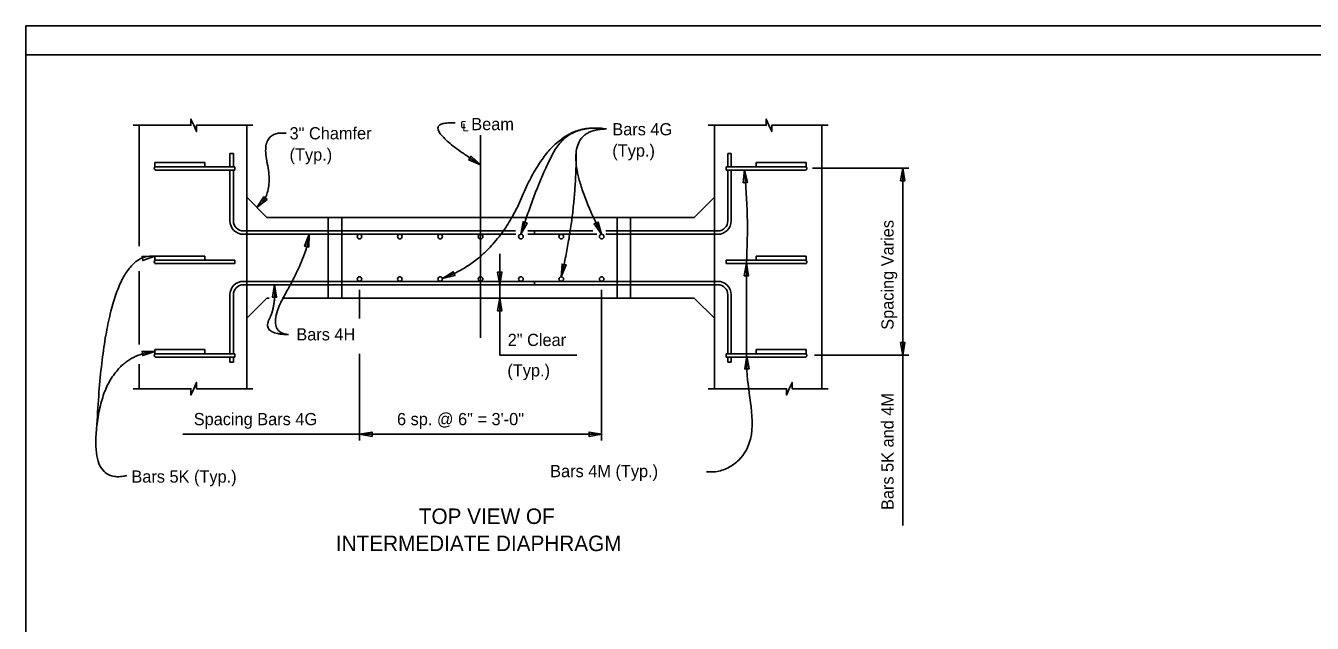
# Model space of a CAD drawing. Extents: x 0 to 30.8, y 0 to 19.8.
# Drawn here: x 0 to 15.94, y 12.4 to 19.8 of the extents above; entities that cross this region are included whole.
import ezdxf

# ---------------------------------------------------------------- set-up
doc = ezdxf.new("R2010")
doc.units = 0
for name, color, linetype in [('ActivePts-ConstElements', 7, 'Continuous'), ('BeamConc', 7, 'Continuous'), ('CL_Major', 7, 'Continuous'), ('Dimension', 7, 'Continuous'), ('Miscellaneous', 7, 'Continuous'), ('Miscellaneous1', 7, 'Continuous'), ('Rebar', 7, 'Continuous'), ('TextStructures', 7, 'Continuous')]:
    doc.layers.add(name, color=color, linetype=linetype)

msp = doc.modelspace()

# ---------------------------------------------------------------- linework, layer by layer
at = {"layer": 'ActivePts-ConstElements'}
msp.add_lwpolyline([(0, 0), (30.765, 0), (30.765, 19.441), (0, 19.441)], close=True, dxfattribs=at)
at = {"layer": 'BeamConc'}
for p, q in [((1.405, 17.069), (1.405, 18.566)), ((2.738, 15.303), (2.738, 18.566)), ((8.53, 18.566), (8.53, 15.303)), ((9.863, 18.566), (9.863, 15.303)), ((2.988, 17.425), (2.738, 17.675)), ((8.53, 17.675), (8.28, 17.425)), ((8.28, 17.425), (2.988, 17.425)), ((1.405, 15.85), (1.405, 16.759)), ((2.988, 16.425), (2.738, 16.175)), ((3.016, 16.425), (2.988, 16.425)), ((8.28, 16.425), (3.175, 16.425)), ((8.53, 16.175), (8.28, 16.425)), ((1.405, 15.303), (1.405, 15.609))]:
    msp.add_line(p, q, dxfattribs=at)
at = {"layer": 'CL_Major'}
msp.add_line((5.634, 15.935), (5.634, 18.446), dxfattribs=at)
at = {"layer": 'Dimension'}
for p, q in [((9.744, 18.035), (10.939, 18.035)), ((10.863, 18.035), (10.863, 13.61)), ((5.872, 16.972), (5.872, 15.719)), ((4.134, 16.528), (4.134, 16.174)), ((7.134, 16.528), (7.134, 14.663)), ((4.134, 15.734), (4.134, 14.663)), ((5.872, 15.719), (6.828, 15.719)), ((9.771, 15.718), (10.939, 15.718)), ((1.945, 14.738), (7.134, 14.738))]:
    msp.add_line(p, q, dxfattribs=at)
for points in [[(2.814, 18.566), (2.115, 18.566), (2.115, 18.488), (2.081, 18.566), (2.047, 18.643), (2.047, 18.566), (1.329, 18.566)], [(9.939, 18.566), (9.24, 18.566), (9.24, 18.489), (9.206, 18.566), (9.172, 18.644), (9.172, 18.566), (8.454, 18.566)], [(2.814, 15.303), (2.115, 15.303), (2.115, 15.38), (2.081, 15.303), (2.047, 15.225), (2.047, 15.303), (1.329, 15.303)], [(9.939, 15.303), (9.492, 15.303), (9.492, 15.38), (9.458, 15.303), (9.424, 15.225), (9.424, 15.303), (8.454, 15.303)]]:
    msp.add_lwpolyline(points, dxfattribs=at)
for points in [[(5.634, 18.077), (5.516, 18.183), (5.488, 18.138)], [(8.904, 18.013), (8.887, 17.855), (8.94, 17.858)], [(10.863, 18.035), (10.89, 17.879), (10.837, 17.879)], [(2.863, 17.55), (2.951, 17.682), (2.989, 17.646)], [(6.134, 17.216), (6.161, 17.372), (6.211, 17.355)], [(3.509, 17.216), (3.454, 17.068), (3.506, 17.058)], [(3.509, 17.216), (3.509, 17.216), (3.509, 17.216)], [(7.134, 17.216), (7.041, 17.345), (7.089, 17.368)], [(1.599, 16.943), (1.441, 16.942), (1.45, 16.89)], [(5.162, 16.67), (5.316, 16.704), (5.296, 16.753)], [(5.872, 16.591), (5.898, 16.748), (5.845, 16.748)], [(6.634, 16.69), (6.696, 16.836), (6.644, 16.848)], [(8.928, 16.859), (8.901, 16.703), (8.954, 16.703)], [(3.082, 16.592), (3.108, 16.436), (3.055, 16.436)], [(5.872, 16.425), (5.845, 16.269), (5.898, 16.269)], [(10.863, 15.718), (10.837, 15.874), (10.89, 15.874)], [(1.599, 15.766), (1.441, 15.765), (1.45, 15.713)], [(8.932, 15.705), (8.906, 15.548), (8.959, 15.548)], [(8.932, 15.705), (8.932, 15.704), (8.932, 15.704)], [(4.134, 14.738), (4.29, 14.765), (4.29, 14.712)], [(7.134, 14.738), (6.978, 14.712), (6.978, 14.765)]]:
    msp.add_lwpolyline(points, close=True, dxfattribs=at)
for points in [[(5.634, 18.077), (4.768, 18.625), (5.321, 18.595)], [(5.162, 16.67), (5.823, 16.905), (6.49, 18.495), (6.985, 18.529)], [(6.134, 17.216), (6.339, 17.859), (6.73, 18.591), (7.195, 18.521)], [(7.134, 17.216), (6.465, 18.521), (7.195, 18.521)], [(2.863, 17.55), (3.077, 17.701), (2.903, 18.503), (3.228, 18.468)], [(6.634, 16.69), (6.819, 17.473), (6.819, 18.24)], [(3.509, 17.216), (3.495, 16.974), (2.948, 16.004), (3.254, 15.974)], [(1.599, 16.943), (0.986, 17.02), (0.882, 14.859)], [(3.082, 16.591), (3.101, 16.334), (2.927, 15.979), (3.254, 15.974)], [(1.599, 15.766), (1.001, 15.7), (0.777, 14.116), (1.251, 14.226)]]:
    msp.add_open_spline(points, degree=2, dxfattribs=at)
for points in [[(8.904, 18.013), (8.938, 17.446), (8.928, 16.857)], [(8.928, 16.859), (8.928, 16.322), (8.928, 15.694)], [(8.932, 15.705), (8.932, 15.583), (8.977, 15.134), (8.977, 14.679), (8.833, 14.419), (8.699, 14.324), (8.546, 14.275), (8.434, 14.275)]]:
    msp.add_spline(points, degree=3, dxfattribs=at)
at = {"layer": 'Miscellaneous'}
for p, q in [((3.748, 17.425), (3.748, 16.425)), ((3.915, 17.425), (3.915, 16.425)), ((7.326, 17.425), (7.326, 16.425)), ((7.493, 17.425), (7.493, 16.425))]:
    msp.add_line(p, q, dxfattribs=at)
at = {"layer": 'Miscellaneous1'}
msp.add_lwpolyline([(0, 19.8), (30.8, 19.8), (30.8, 0), (0, 0)], close=True, dxfattribs=at)
at = {"layer": 'Rebar'}
for p, q in [((2.53, 18.216), (2.572, 18.216)), ((2.53, 18.053), (2.53, 18.216)), ((2.572, 18.053), (2.572, 18.216)), ((8.738, 18.216), (8.697, 18.216)), ((8.697, 18.216), (8.697, 18.053)), ((8.738, 18.216), (8.738, 18.053)), ((1.599, 18.053), (1.599, 18.105)), ((1.599, 18.105), (2.219, 18.105)), ((1.599, 18.053), (2.592, 18.053)), ((1.613, 18.011), (2.592, 18.011)), ((2.219, 18.053), (2.219, 18.105)), ((2.53, 17.383), (2.53, 18.011)), ((2.572, 17.383), (2.572, 18.011)), ((2.592, 18.011), (2.592, 18.053)), ((9.669, 18.053), (8.676, 18.053)), ((8.676, 18.011), (8.676, 18.053)), ((9.655, 18.011), (8.676, 18.011)), ((8.697, 18.011), (8.697, 17.383)), ((8.738, 18.011), (8.738, 17.383)), ((9.669, 18.105), (9.049, 18.105)), ((9.049, 18.053), (9.049, 18.105)), ((9.669, 18.053), (9.669, 18.105)), ((6.071, 17.216), (2.696, 17.216)), ((6.068, 17.258), (2.697, 17.258)), ((7.025, 17.258), (6.221, 17.258)), ((7.075, 17.216), (6.221, 17.216)), ((6.301, 17.216), (6.301, 17.258)), ((8.572, 17.258), (7.185, 17.258)), ((8.572, 17.216), (7.185, 17.216)), ((1.599, 16.894), (1.599, 16.946)), ((1.599, 16.946), (2.219, 16.946)), ((1.599, 16.894), (2.592, 16.894)), ((2.219, 16.894), (2.219, 16.946)), ((2.592, 16.853), (2.592, 16.894)), ((9.669, 16.894), (8.676, 16.894)), ((8.676, 16.853), (8.676, 16.894)), ((9.669, 16.946), (9.049, 16.946)), ((9.049, 16.894), (9.049, 16.946)), ((9.669, 16.894), (9.669, 16.946)), ((1.613, 16.853), (2.592, 16.853)), ((9.655, 16.853), (8.676, 16.853)), ((8.572, 16.633), (2.696, 16.633)), ((8.572, 16.591), (2.697, 16.591)), ((6.301, 16.591), (6.301, 16.633)), ((2.53, 16.467), (2.53, 15.736)), ((2.572, 16.466), (2.572, 15.736)), ((8.697, 15.736), (8.697, 16.466)), ((8.738, 15.736), (8.738, 16.467)), ((1.599, 15.736), (1.599, 15.788)), ((1.599, 15.788), (2.219, 15.788)), ((2.219, 15.736), (2.219, 15.788)), ((9.669, 15.788), (9.049, 15.788)), ((9.049, 15.736), (9.049, 15.788)), ((9.669, 15.736), (9.669, 15.788)), ((1.599, 15.736), (2.592, 15.736)), ((1.613, 15.694), (2.592, 15.694)), ((2.53, 15.694), (2.53, 15.633)), ((2.53, 15.633), (2.572, 15.633)), ((2.572, 15.694), (2.572, 15.633)), ((2.592, 15.694), (2.592, 15.736)), ((9.669, 15.736), (8.676, 15.736)), ((8.676, 15.694), (8.676, 15.736)), ((9.655, 15.694), (8.676, 15.694)), ((8.697, 15.633), (8.697, 15.694)), ((8.738, 15.633), (8.697, 15.633)), ((8.738, 15.633), (8.738, 15.694))]:
    msp.add_line(p, q, dxfattribs=at)
for centre in [(4.134, 17.188), (4.634, 17.188), (5.134, 17.188), (5.634, 17.188), (6.134, 17.188), (6.634, 17.188), (7.134, 17.188), (4.134, 16.662), (4.634, 16.662), (5.134, 16.662), (5.634, 16.662), (6.134, 16.662), (6.634, 16.662), (7.134, 16.662)]:
    msp.add_circle(centre, 0.0286, dxfattribs=at)
for centre, radius, start, end in [((1.613, 18.032), 0.0209, 81.4319, 269.9425), ((9.655, 18.032), 0.0209, 270.0575, 98.5681), ((2.697, 17.383), 0.167, 180, 270), ((2.697, 17.383), 0.125, 180, 270), ((8.572, 17.383), 0.125, 270, 360), ((8.572, 17.383), 0.167, 270, 360), ((1.613, 16.873), 0.0209, 81.4319, 269.9425), ((9.655, 16.873), 0.0209, 270.0575, 98.5681), ((2.697, 16.466), 0.167, 90, 180), ((2.697, 16.466), 0.125, 90, 180), ((8.572, 16.466), 0.167, 0, 90), ((8.572, 16.466), 0.125, 0, 90), ((1.613, 15.715), 0.0209, 81.4319, 269.9425), ((9.655, 15.715), 0.0209, 270.0575, 98.5681)]:
    msp.add_arc(centre, radius, start, end, dxfattribs=at)

# ---------------------------------------------------------------- texts
at = {"layer": 'Dimension'}
for s, height, p in [('3" Chamfer', 0.1512, (3.268, 18.392)), ('Bars 4G', 0.1512, (7.266, 18.442)), ('(Typ.)', 0.1512, (7.266, 18.178)), ('(Typ.)', 0.1512, (3.268, 18.128)), ('TOP VIEW OF', 0.192, (4.869, 13.627)), ('INTERMEDIATE DIAPHRAGM', 0.192, (3.842, 13.291))]:
    msp.add_text(s, height=height, dxfattribs=at).set_placement(p)
at = {"layer": 'TextStructures'}
for s, p in [('℄ Beam', (5.381, 18.506)), ('Bars 4H', (3.352, 15.901)), ('2" Clear', (5.97, 15.832)), ('(Typ.)', (5.966, 15.455)), ('Spacing Bars 4G', (2.081, 14.851)), ('6 sp. @ 6" = 3\'-0"', (4.599, 14.851)), ('Bars 4M (Typ.)', (6.496, 14.207)), ('Bars 5K (Typ.)', (1.309, 14.139))]:
    msp.add_text(s, height=0.1512, dxfattribs=at).set_placement(p)
for s, p in [('Spacing Varies', (10.75, 16.033)), ('Bars 5K and 4M', (10.75, 13.8))]:
    msp.add_text(s, height=0.1512, rotation=90, dxfattribs=at).set_placement(p)

doc.saveas('drawing.dxf')
